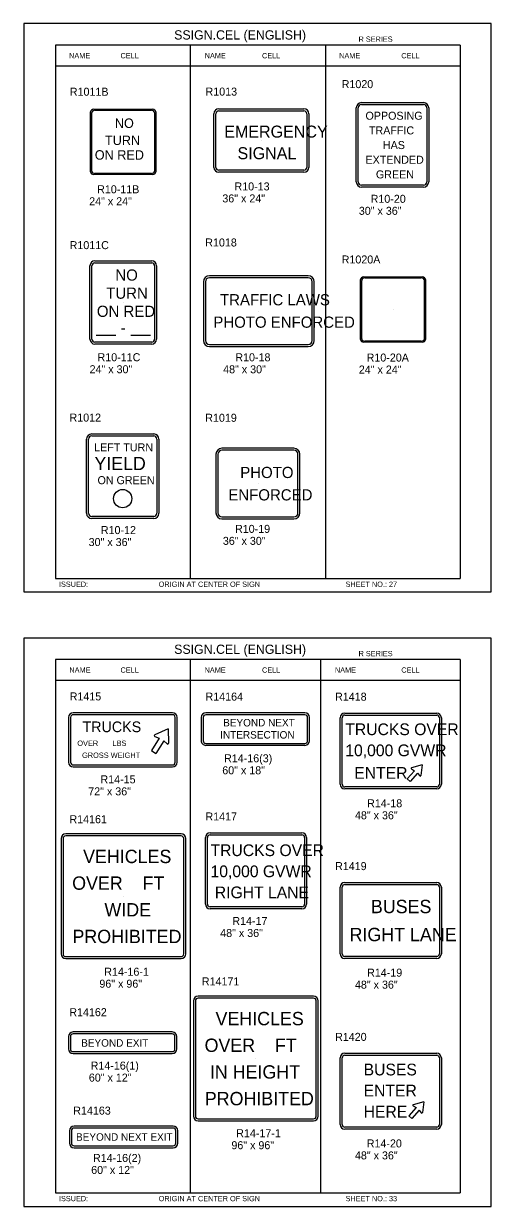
# Model space of a CAD drawing. Extents: x -5299 to 22597, y -19549 to -1808.
# Drawn here: x -3651 to -2950, y -8230 to -6456 of the extents above; entities that cross this region are included whole.
import ezdxf

# ---------------------------------------------------------------- set-up
doc = ezdxf.new("R2010")
doc.units = 0
for name, color, linetype in [('Level 1', 7, 'Continuous'), ('Level 2', 7, 'Continuous'), ('Level 3', 7, 'Continuous'), ('Level 63', 7, 'Continuous')]:
    doc.layers.add(name, color=color, linetype=linetype)

msp = doc.modelspace()

# ---------------------------------------------------------------- linework, layer by layer
at = {"layer": 'Level 1'}
for p, q in [((-2996.6, -6488.6), (-3603.6, -6488.6)), ((-3603.6, -6488.6), (-3603.6, -7288.6)), ((-3401.3, -6488.6), (-3401.3, -7288.6)), ((-3198.9, -6488.6), (-3198.9, -7288.6)), ((-2996.6, -6488.6), (-2996.6, -7288.6)), ((-2996.6, -6520.3), (-3603.6, -6520.3)), ((-3144.7, -6577.8), (-3051.8, -6577.8)), ((-3548.9, -6677.5), (-3548.9, -6589.9)), ((-3544.4, -6586.3), (-3459.5, -6586.3)), ((-3455, -6589.9), (-3455, -6677.5)), ((-3362.9, -6671.9), (-3362.9, -6591.5)), ((-3358.6, -6587.2), (-3231, -6587.2)), ((-3226.7, -6591.5), (-3226.7, -6671.9)), ((-3149.5, -6693.8), (-3149.5, -6582.6)), ((-3047, -6582.6), (-3047, -6693.8)), ((-3502, -6633.7), (-3502, -6633.7)), ((-3294.8, -6631.7), (-3294.8, -6631.7)), ((-3098.3, -6638.2), (-3098.3, -6638.2)), ((-3459.5, -6681.1), (-3544.4, -6681.1)), ((-3231, -6676.2), (-3358.6, -6676.2)), ((-3051.8, -6698.6), (-3144.7, -6698.6)), ((-3548.7, -6929.6), (-3548.7, -6819.6)), ((-3544.3, -6815.2), (-3459.2, -6815.2)), ((-3454.8, -6819.6), (-3454.8, -6929.6)), ((-3378.6, -6843.6), (-3378.6, -6931.6)), ((-3224.6, -6837.6), (-3372.6, -6837.6)), ((-3218.6, -6931.6), (-3218.6, -6843.6)), ((-3144.4, -6929), (-3144.4, -6841.4)), ((-3139.9, -6837.8), (-3055, -6837.8)), ((-3050.5, -6841.4), (-3050.5, -6929)), ((-3298.6, -6887.4), (-3298.6, -6887.4)), ((-3097.4, -6885.2), (-3097.4, -6885.2)), ((-3459.2, -6934), (-3544.3, -6934)), ((-3055, -6932.7), (-3139.9, -6932.7)), ((-3372.6, -6937.6), (-3224.6, -6937.6)), ((-3549.1, -7074.8), (-3456.2, -7074.8)), ((-3553.9, -7190.8), (-3553.9, -7079.6)), ((-3451.4, -7079.6), (-3451.4, -7190.8)), ((-3359.9, -7102.2), (-3359.9, -7190.2)), ((-3245.9, -7096.2), (-3353.9, -7096.2)), ((-3239.9, -7190.2), (-3239.9, -7102.2)), ((-3502.7, -7135.2), (-3502.7, -7135.2)), ((-3299.8, -7146.2), (-3299.8, -7146.2)), ((-3456.2, -7195.6), (-3549.1, -7195.6)), ((-3353.9, -7196.2), (-3245.9, -7196.2)), ((-3603.6, -7288.6), (-2996.6, -7288.6)), ((-2996.6, -7410), (-3603.6, -7410)), ((-3603.6, -7410), (-3603.6, -8210)), ((-3401.3, -7410), (-3401.3, -8210)), ((-3206.1, -7410), (-3206.1, -8210)), ((-2996.6, -7410), (-2996.6, -8210)), ((-2996.6, -7441.7), (-3603.6, -7441.7)), ((-3580.8, -7496.8), (-3580.8, -7564.2)), ((-3428, -7492.8), (-3576.8, -7492.8)), ((-3424, -7564.2), (-3424, -7496.8)), ((-3382, -7497), (-3382, -7531.8)), ((-3229.4, -7493), (-3378, -7493)), ((-3225.4, -7531.8), (-3225.4, -7497)), ((-3173.7, -7597.2), (-3173.7, -7497.4)), ((-3169.7, -7493.4), (-3032, -7493.4)), ((-3028, -7497.4), (-3028, -7597.2)), ((-3434.7, -7514.2), (-3454.6, -7523.1)), ((-3434.7, -7514.2), (-3434, -7535.6)), ((-3303.7, -7506.3), (-3303.7, -7506.3)), ((-3502.4, -7530.5), (-3502.4, -7530.5)), ((-3448, -7528), (-3459.6, -7546.6)), ((-3454.5, -7525.3), (-3448, -7528)), ((-3441.2, -7532.2), (-3452.8, -7550.9)), ((-3441.2, -7532.2), (-3435.9, -7536.6)), ((-3378, -7535.8), (-3229.4, -7535.8)), ((-3459.6, -7546.6), (-3452.8, -7550.9)), ((-3100.9, -7547.3), (-3100.9, -7547.3)), ((-3576.8, -7568.2), (-3428, -7568.2)), ((-3069.8, -7574), (-3065.2, -7576.8)), ((-3053.7, -7568.2), (-3069.5, -7572.4)), ((-3053.7, -7568.2), (-3055.8, -7584.1)), ((-3065.2, -7576.8), (-3076.1, -7589.2)), ((-3076.1, -7589.2), (-3071.6, -7593.1)), ((-3060.7, -7580.7), (-3071.6, -7593.1)), ((-3060.7, -7580.7), (-3057.4, -7584.6)), ((-3032, -7601.2), (-3169.7, -7601.2)), ((-3592.1, -7678.7), (-3592.1, -7851.7)), ((-3415.2, -7674.7), (-3588.1, -7674.7)), ((-3411.2, -7851.7), (-3411.2, -7678.7)), ((-3375.7, -7776.9), (-3375.7, -7677.1)), ((-3371.7, -7673.1), (-3234, -7673.1)), ((-3230, -7677.1), (-3230, -7776.9)), ((-3302.8, -7727), (-3302.8, -7727)), ((-3169.7, -7747.5), (-3032, -7747.5)), ((-3501.6, -7765.2), (-3501.6, -7765.2)), ((-3173.7, -7851.3), (-3173.7, -7751.5)), ((-3028, -7751.5), (-3028, -7851.3)), ((-3234, -7780.9), (-3371.7, -7780.9)), ((-3100.9, -7801.4), (-3100.9, -7801.4)), ((-3588.1, -7855.7), (-3415.2, -7855.7)), ((-3032, -7855.3), (-3169.7, -7855.3)), ((-3393.6, -7922), (-3393.6, -8094.9)), ((-3216.7, -7918), (-3389.6, -7918)), ((-3212.7, -8094.9), (-3212.7, -7922)), ((-3581, -7975.7), (-3581, -7994.2)), ((-3428.4, -7971.7), (-3577, -7971.7)), ((-3424.4, -7994.2), (-3424.4, -7975.7)), ((-3577, -7998.2), (-3428.4, -7998.2)), ((-3502.7, -7985), (-3502.7, -7985)), ((-3303.2, -8008.4), (-3303.2, -8008.4)), ((-3173.7, -8107.4), (-3173.7, -8007.6)), ((-3169.7, -8003.6), (-3032, -8003.6)), ((-3028, -8007.6), (-3028, -8107.4)), ((-3100.9, -8057.5), (-3100.9, -8057.5)), ((-3062.8, -8082.1), (-3073.7, -8094.5)), ((-3058.3, -8086.1), (-3069.2, -8098.5)), ((-3067.4, -8079.4), (-3062.8, -8082.1)), ((-3051.3, -8073.6), (-3067.1, -8077.7)), ((-3058.3, -8086.1), (-3055, -8090)), ((-3051.3, -8073.6), (-3053.4, -8089.5)), ((-3389.6, -8098.9), (-3216.7, -8098.9)), ((-3073.7, -8094.5), (-3069.2, -8098.5)), ((-3579.5, -8116.8), (-3579.5, -8135.3)), ((-3427, -8112.8), (-3575.5, -8112.8)), ((-3423, -8135.3), (-3423, -8116.8)), ((-3032, -8111.4), (-3169.7, -8111.4)), ((-3575.5, -8139.3), (-3427, -8139.3)), ((-3501.2, -8126.1), (-3501.2, -8126.1)), ((-3603.6, -8210), (-2996.6, -8210))]:
    msp.add_line(p, q, dxfattribs=at)
msp.add_circle((-3502.7, -7168.7), 13.7, dxfattribs=at)
for centre, radius, start, end in [((-3144.7, -6582.6), 4.8, 90, 180), ((-3051.8, -6582.6), 4.8, 0, 90), ((-3358.6, -6591.5), 4.32, 90, 180), ((-3231, -6591.5), 4.32, 0, 90), ((-3358.6, -6671.9), 4.32, 180, 270), ((-3231, -6671.9), 4.32, 270, 0), ((-3144.7, -6693.8), 4.8, 180, 270), ((-3051.8, -6693.8), 4.8, 270, 0), ((-3544.3, -6819.6), 4.4, 90, 180), ((-3459.2, -6819.6), 4.4, 0, 90), ((-3372.6, -6843.6), 6, 90, 180), ((-3224.6, -6843.6), 6, 0, 90), ((-3544.3, -6929.6), 4.4, 180, 270), ((-3459.2, -6929.6), 4.4, 270, 0), ((-3372.6, -6931.6), 6, 180, 270), ((-3224.6, -6931.6), 6, 270, 0), ((-3549.1, -7079.6), 4.8, 90, 180), ((-3456.2, -7079.6), 4.8, 0, 90), ((-3353.9, -7102.2), 6, 90, 180), ((-3245.9, -7102.2), 6, 0, 90), ((-3549.1, -7190.8), 4.8, 180, 270), ((-3456.2, -7190.8), 4.8, 270, 0), ((-3353.9, -7190.2), 6, 180, 270), ((-3245.9, -7190.2), 6, 270, 0), ((-3576.8, -7496.8), 4, 90, 180), ((-3428, -7496.8), 4, 0, 90), ((-3378, -7497), 4, 90, 180), ((-3229.4, -7497), 4, 0, 90), ((-3169.7, -7497.4), 4, 90, 180), ((-3032, -7497.4), 4, 0, 90), ((-3454.1, -7524.2), 1.2, 114.124, 248.3476), ((-3435.2, -7535.6), 1.2, 230.0779, 1.968), ((-3378, -7531.8), 4, 180.001, 270), ((-3229.4, -7531.8), 4, 270, 0), ((-3576.8, -7564.2), 4, 180, 270), ((-3428, -7564.2), 4, 270, 0), ((-3069.3, -7573.3), 0.9, 104.7504, 238.9741), ((-3056.7, -7584), 0.9, 220.7043, 352.5945), ((-3169.7, -7597.2), 4, 180, 270), ((-3032, -7597.2), 4, 270, 0), ((-3588.1, -7678.7), 4, 90, 180), ((-3415.2, -7678.7), 4, 0, 90), ((-3371.7, -7677.1), 4, 90, 180), ((-3234, -7677.1), 4, 0, 90), ((-3169.7, -7751.5), 4, 90, 180), ((-3032, -7751.5), 4, 0, 90), ((-3371.7, -7776.9), 4, 180, 270), ((-3234, -7776.9), 4, 270, 0), ((-3588.1, -7851.7), 4, 180, 270), ((-3415.2, -7851.7), 4, 270, 0), ((-3169.7, -7851.3), 4, 180, 270), ((-3032, -7851.3), 4, 270, 0), ((-3389.6, -7922), 4, 90, 180), ((-3216.7, -7922), 4, 0, 90), ((-3577, -7975.7), 4, 90, 180), ((-3428.4, -7975.7), 4, 0, 90), ((-3577, -7994.2), 4, 180, 270), ((-3428.4, -7994.2), 4, 270, 0), ((-3169.7, -8007.6), 4, 90, 180), ((-3032, -8007.6), 4, 0, 90), ((-3066.9, -8078.6), 0.9, 104.7504, 238.9741), ((-3389.6, -8094.9), 4, 180, 270), ((-3216.7, -8094.9), 4, 270, 0), ((-3054.3, -8089.4), 0.9, 220.7043, 352.5945), ((-3575.5, -8116.8), 4, 90, 180), ((-3427, -8116.8), 4, 0, 90), ((-3169.7, -8107.4), 4, 180, 270), ((-3032, -8107.4), 4, 270, 0), ((-3575.5, -8135.3), 4, 180, 270), ((-3427, -8135.3), 4, 270, 0)]:
    msp.add_arc(centre, radius, start, end, dxfattribs=at)
for centre, major_axis, start_param, end_param in [((-3544.4, -6589.9), (-4.51, 0), 4.712389, 6.283185), ((-3459.5, -6589.9), (-4.51, 0), 3.141593, 4.712389), ((-3544.4, -6677.5), (4.51, 0), 3.141593, 4.712389), ((-3459.5, -6677.5), (4.51, 0), 4.712389, 6.283185), ((-3139.9, -6841.4), (-4.51, 0), 4.712389, 6.283185), ((-3055, -6841.4), (-4.51, 0), 3.141593, 4.712389), ((-3139.9, -6929), (4.51, 0), 3.141593, 4.712389), ((-3055, -6929), (4.51, 0), 4.712389, 6.283185)]:
    msp.add_ellipse(centre, major_axis=major_axis, ratio=0.802018, start_param=start_param, end_param=end_param, dxfattribs=at)
at = {"layer": 'Level 3'}
for p, q in [((-3144.7, -6574.8), (-3051.8, -6574.8)), ((-3550.7, -6678.7), (-3550.7, -6588.7)), ((-3545.9, -6584.8), (-3458.1, -6584.8)), ((-3453.2, -6588.7), (-3453.2, -6678.7)), ((-3365.9, -6671.9), (-3365.9, -6591.5)), ((-3358.6, -6584.2), (-3231, -6584.2)), ((-3223.7, -6591.5), (-3223.7, -6671.9)), ((-3152.5, -6693.8), (-3152.5, -6582.6)), ((-3044, -6582.6), (-3044, -6693.8)), ((-3458.1, -6682.6), (-3545.9, -6682.6)), ((-3231, -6679.2), (-3358.6, -6679.2)), ((-3051.8, -6701.6), (-3144.7, -6701.6)), ((-3551.7, -6929.6), (-3551.7, -6819.6)), ((-3544.3, -6812.2), (-3459.2, -6812.2)), ((-3451.8, -6819.6), (-3451.8, -6929.6)), ((-3381.6, -6843.6), (-3381.6, -6931.6)), ((-3224.6, -6834.6), (-3372.6, -6834.6)), ((-3215.6, -6931.6), (-3215.6, -6843.6)), ((-3146.2, -6930.2), (-3146.2, -6840.2)), ((-3141.3, -6836.3), (-3053.5, -6836.3)), ((-3048.6, -6840.2), (-3048.6, -6930.2)), ((-3501.8, -6874.6), (-3501.8, -6874.6)), ((-3542.3, -6923.4), (-3513, -6923.4)), ((-3490.6, -6923.4), (-3461.2, -6923.4)), ((-3053.5, -6934.1), (-3141.3, -6934.1)), ((-3459.2, -6937), (-3544.3, -6937)), ((-3372.6, -6940.6), (-3224.6, -6940.6)), ((-3549.1, -7071.8), (-3456.2, -7071.8)), ((-3556.9, -7190.8), (-3556.9, -7079.6)), ((-3448.4, -7079.6), (-3448.4, -7190.8)), ((-3245.9, -7093.2), (-3353.9, -7093.2)), ((-3362.9, -7102.2), (-3362.9, -7190.2)), ((-3236.9, -7190.2), (-3236.9, -7102.2)), ((-3456.2, -7198.6), (-3549.1, -7198.6)), ((-3353.9, -7199.2), (-3245.9, -7199.2)), ((-3583.8, -7496.8), (-3583.8, -7564.2)), ((-3428, -7489.8), (-3576.8, -7489.8)), ((-3421, -7564.2), (-3421, -7496.8)), ((-3385, -7497), (-3385, -7531.8)), ((-3229.4, -7490), (-3378, -7490)), ((-3222.4, -7531.8), (-3222.4, -7497)), ((-3176.7, -7597.2), (-3176.7, -7497.4)), ((-3169.7, -7490.4), (-3032, -7490.4)), ((-3025, -7497.4), (-3025, -7597.2)), ((-3229.4, -7538.8), (-3378, -7538.8)), ((-3576.8, -7571.2), (-3428, -7571.2)), ((-3032, -7604.2), (-3169.7, -7604.2)), ((-3595.1, -7678.7), (-3595.1, -7851.7)), ((-3415.2, -7671.7), (-3588.1, -7671.7)), ((-3408.2, -7851.7), (-3408.2, -7678.7)), ((-3378.7, -7776.9), (-3378.7, -7677.1)), ((-3371.7, -7670.1), (-3234, -7670.1)), ((-3227, -7677.1), (-3227, -7776.9)), ((-3169.7, -7744.5), (-3032, -7744.5)), ((-3176.7, -7851.3), (-3176.7, -7751.5)), ((-3025, -7751.5), (-3025, -7851.3)), ((-3234, -7783.9), (-3371.7, -7783.9)), ((-3588.1, -7858.7), (-3415.2, -7858.7)), ((-3032, -7858.3), (-3169.7, -7858.3)), ((-3396.6, -7922), (-3396.6, -8094.9)), ((-3216.7, -7915), (-3389.6, -7915)), ((-3209.7, -8094.9), (-3209.7, -7922)), ((-3584, -7975.7), (-3584, -7994.2)), ((-3428.4, -7968.7), (-3577, -7968.7)), ((-3421.4, -7994.2), (-3421.4, -7975.7)), ((-3577, -8001.2), (-3428.4, -8001.2)), ((-3176.7, -8107.4), (-3176.7, -8007.6)), ((-3169.7, -8000.6), (-3032, -8000.6)), ((-3025, -8007.6), (-3025, -8107.4)), ((-3389.6, -8101.9), (-3216.7, -8101.9)), ((-3582.5, -8116.8), (-3582.5, -8135.3)), ((-3427, -8109.8), (-3575.5, -8109.8)), ((-3420, -8135.3), (-3420, -8116.8)), ((-3032, -8114.4), (-3169.7, -8114.4)), ((-3575.5, -8142.3), (-3427, -8142.3))]:
    msp.add_line(p, q, dxfattribs=at)
for centre, radius, start, end in [((-3144.7, -6582.6), 7.8, 90, 180), ((-3051.8, -6582.6), 7.8, 0, 90), ((-3358.6, -6591.5), 7.32, 90, 180), ((-3231, -6591.5), 7.32, 0, 90), ((-3358.6, -6671.9), 7.32, 180, 270), ((-3231, -6671.9), 7.32, 270, 0), ((-3144.7, -6693.8), 7.8, 180, 270), ((-3051.8, -6693.8), 7.8, 270, 0), ((-3544.3, -6819.6), 7.4, 90, 180), ((-3459.2, -6819.6), 7.4, 0, 90), ((-3372.6, -6843.6), 9, 90, 180), ((-3224.6, -6843.6), 9, 0, 90), ((-3544.3, -6929.6), 7.4, 180, 270), ((-3459.2, -6929.6), 7.4, 270, 0), ((-3372.6, -6931.6), 9, 180, 270), ((-3224.6, -6931.6), 9, 270, 0), ((-3549.1, -7079.6), 7.8, 90, 180), ((-3456.2, -7079.6), 7.8, 0, 90), ((-3353.9, -7102.2), 9, 90, 180), ((-3245.9, -7102.2), 9, 0, 90), ((-3549.1, -7190.8), 7.8, 180, 270), ((-3456.2, -7190.8), 7.8, 270, 0), ((-3353.9, -7190.2), 9, 180, 270), ((-3245.9, -7190.2), 9, 270, 0), ((-3576.8, -7496.8), 7, 90, 180), ((-3428, -7496.8), 7, 0, 90), ((-3378, -7497), 7, 90, 180), ((-3229.4, -7497), 7, 0, 90), ((-3169.7, -7497.4), 7, 90, 180), ((-3032, -7497.4), 7, 0, 90), ((-3378, -7531.8), 7, 179.9992, 270), ((-3229.4, -7531.8), 7, 270, 0), ((-3576.8, -7564.2), 7, 180, 270), ((-3428, -7564.2), 7, 270, 0), ((-3169.7, -7597.2), 7, 180, 270), ((-3032, -7597.2), 7, 270, 0), ((-3588.1, -7678.7), 7, 90, 180), ((-3415.2, -7678.7), 7, 0, 90), ((-3371.7, -7677.1), 7, 90, 180), ((-3234, -7677.1), 7, 0, 90), ((-3169.7, -7751.5), 7, 90, 180), ((-3032, -7751.5), 7, 0, 90), ((-3371.7, -7776.9), 7, 180, 270), ((-3234, -7776.9), 7, 270, 0), ((-3588.1, -7851.7), 7, 180, 270), ((-3415.2, -7851.7), 7, 270, 0), ((-3169.7, -7851.3), 7, 180, 270), ((-3032, -7851.3), 7, 270, 0), ((-3389.6, -7922), 7, 90, 180), ((-3216.7, -7922), 7, 0, 90), ((-3577, -7975.7), 7, 90, 180), ((-3428.4, -7975.7), 7, 0, 90), ((-3577, -7994.2), 7, 180, 270), ((-3428.4, -7994.2), 7, 270, 0), ((-3169.7, -8007.6), 7, 90, 180), ((-3032, -8007.6), 7, 0, 90), ((-3389.6, -8094.9), 7, 180, 270), ((-3216.7, -8094.9), 7, 270, 0), ((-3575.5, -8116.8), 7, 90, 180), ((-3427, -8116.8), 7, 0, 90), ((-3169.7, -8107.4), 7, 180, 270), ((-3032, -8107.4), 7, 270, 0), ((-3575.5, -8135.3), 7, 180, 270), ((-3427, -8135.3), 7, 270, 0)]:
    msp.add_arc(centre, radius, start, end, dxfattribs=at)
for centre, major_axis, start_param, end_param in [((-3545.9, -6588.7), (-4.88, 0), 4.712389, 6.283185), ((-3458.1, -6588.7), (-4.88, 0), 3.141593, 4.712389), ((-3545.9, -6678.7), (4.88, 0), 3.141593, 4.712389), ((-3458.1, -6678.7), (4.88, 0), 4.712389, 6.283185), ((-3141.3, -6840.2), (-4.88, 0), 4.712389, 6.283185), ((-3053.5, -6840.2), (-4.88, 0), 3.141593, 4.712389), ((-3141.3, -6930.2), (4.88, 0), 3.141593, 4.712389), ((-3053.5, -6930.2), (4.88, 0), 4.712389, 6.283185)]:
    msp.add_ellipse(centre, major_axis=major_axis, ratio=0.802018, start_param=start_param, end_param=end_param, dxfattribs=at)
at = {"layer": 'Level 63'}
for points in [[(-3651.1, -7308.8), (-2950.1, -7308.8), (-2950.1, -6456.4), (-3651.1, -6456.4)], [(-3651.1, -8230.2), (-2950.1, -8230.2), (-2950.1, -7377.8), (-3651.1, -7377.8)]]:
    msp.add_lwpolyline(points, close=True, dxfattribs=at)

# ---------------------------------------------------------------- texts
at = {"layer": 'Level 1'}
for s, height, p in [('NO', 14.18, (-3514.4, -6612.8)), ('TURN', 14.18, (-3529.2, -6638.4)), ('ON RED', 14.18, (-3544.5, -6660.4)), ('TRAFFIC LAWS', 16.8, (-3356.8, -6878.9)), ('PHOTO ENFORCED', 16.8, (-3366.8, -6912.5)), ('LEFT TURN', 12, (-3545.4, -7097.8)), ('YIELD', 19.91, (-3545, -7126)), ('PHOTO', 16.8, (-3326.5, -7137.9)), ('ON GREEN', 12, (-3540.4, -7147.1)), ('ENFORCED', 16.8, (-3344.3, -7171.5)), ('TRUCKS', 16, (-3562.9, -7519)), ('BEYOND NEXT', 11.2, (-3352.1, -7510.4)), ('INTERSECTION', 11.2, (-3356.5, -7528.6)), ('TRUCKS OVER', 17.6, (-3169, -7523.5)), ('OVER       LBS', 8, (-3570.7, -7539.6)), ('10,000 GVWR', 17.6, (-3169, -7555.1)), ('GROSS WEIGHT', 8, (-3563.6, -7557.6)), ('ENTER', 17.6, (-3155.5, -7589)), ('VEHICLES', 20, (-3562, -7715.4)), ('TRUCKS OVER', 17.6, (-3371, -7704.9)), ('10,000 GVWR', 17.6, (-3371, -7736.5)), ('OVER    FT', 20, (-3578.4, -7755.4)), ('RIGHT LANE', 17.6, (-3364.6, -7768.1)), ('WIDE', 20, (-3530, -7795.4)), ('BUSES', 20, (-3130.6, -7790.5)), ('PROHIBITED', 20, (-3578, -7835.4)), ('RIGHT LANE', 20, (-3162.6, -7832.5)), ('VEHICLES', 20, (-3363.5, -7958.6)), ('BEYOND EXIT   ', 11.2, (-3564.9, -7990.7)), ('OVER    FT', 20, (-3379.9, -7998.6)), ('BUSES', 17.6, (-3141.5, -8033.8)), ('IN HEIGHT', 20, (-3371.9, -8038.6)), ('ENTER', 17.6, (-3141.5, -8065.4)), ('PROHIBITED', 20, (-3379.6, -8078.6)), ('HERE', 17.6, (-3141.5, -8097)), ('BEYOND NEXT EXIT', 11.2, (-3572.6, -8131.8))]:
    msp.add_text(s, height=height, dxfattribs=at).set_placement(p)
at = {"layer": 'Level 2'}
for s, p in [('R1020', (-3174.4, -6553.1)), ('R1011B', (-3581.9, -6564.5)), ('R1013', (-3378.5, -6564.3)), ('R10-11B', (-3541, -6710.8)), ('R10-13', (-3335.1, -6706.5)), ('24" x 24"', (-3552.9, -6728.8)), ('36" x 24"', (-3353.3, -6724.5)), ('R10-20', (-3131, -6725.1)), ('30" x 36"', (-3148.7, -6743.1)), ('R1011C', (-3582.2, -6794.6)), ('R1018', (-3378.9, -6790.6)), ('R1020A', (-3174.4, -6816.1)), ('R10-11C', (-3540.4, -6962.7)), ('R10-18', (-3333.8, -6962.8)), ('R10-20A', (-3137, -6963.2)), ('24" x 30"', (-3552.3, -6980.7)), ('48" x 30"', (-3352.1, -6980.8)), ('24" x 24"', (-3148.7, -6981.2)), ('R1012', (-3582.4, -7053.2)), ('R1019', (-3378.9, -7053.5)), ('R10-12', (-3535.4, -7221.9)), ('R10-19', (-3334.3, -7220.1)), ('30" x 36"', (-3553.7, -7239.9)), ('36" x 30"', (-3352.5, -7238.1)), ('R1415', (-3582.1, -7471.4)), ('R14164', (-3378.5, -7471.7)), ('R1418', (-3184.3, -7471.8)), ('R14-16(3)', (-3350.7, -7564.2)), ('60" x 18"', (-3353.4, -7582.2)), ('R14-15', (-3536, -7595.8)), ('72" x 36"', (-3554.3, -7613.8)), ('R14-18', (-3136.3, -7631.7)), ('R14161', (-3582.5, -7655.6)), ('R1417', (-3378.6, -7651.5)), ('48" x 36"', (-3154.5, -7649.7)), ('R1419', (-3184.3, -7725.9)), ('R14-17', (-3338.3, -7808.2)), ('48" x 36"', (-3356.5, -7826.2)), ('R14-16-1', (-3530.3, -7884.3)), ('R14-19', (-3136.3, -7885.7)), ('96" x 96"', (-3537.6, -7902.3)), ('R14171', (-3384, -7898.8)), ('48" x 36"', (-3154.5, -7903.7)), ('R14162', (-3582.7, -7945)), ('R1420', (-3184.3, -7982)), ('R14-16(1)', (-3550.7, -8025.1)), ('60" x 12"', (-3553.4, -8043.1)), ('R14163', (-3576.8, -8092.6)), ('R14-17-1', (-3332.5, -8126.5)), ('96" x 96"', (-3339.7, -8144.5)), ('R14-20', (-3136.8, -8141.8)), ('R14-16(2)', (-3547.2, -8163.6)), ('48" x 36"', (-3154.5, -8159.8)), ('60" x 12"', (-3549.9, -8181.6))]:
    msp.add_text(s, height=12, dxfattribs=at).set_placement(p)
at = {"layer": 'Level 3'}
for s, height, p in [('SSIGN.CEL (ENGLISH)', 13.857, (-3425.5, -6480.2)), ('R SERIES', 7.92, (-3149.1, -6483.6)), ('NAME', 7.92, (-3583, -6508.4)), ('CELL', 7.92, (-3505.9, -6508.4)), ('NAME', 7.92, (-3379.7, -6508.4)), ('CELL', 7.92, (-3293.8, -6508.4)), ('NAME', 7.92, (-3178.2, -6508.4)), ('CELL', 7.92, (-3085, -6508.4)), ('OPPOSING', 12, (-3138.7, -6600.5)), ('EMERGENCY', 18, (-3350.5, -6627.3)), ('TRAFFIC', 12, (-3133.5, -6622.5)), ('HAS', 12, (-3112.6, -6644.5)), ('SIGNAL', 18, (-3330.6, -6659.7)), ('EXTENDED', 12, (-3138.7, -6666.5)), ('GREEN', 12, (-3123.1, -6688.5)), ('NO', 16.8, (-3513.7, -6841.8)), ('TURN', 16.8, (-3527.4, -6869)), ('ON RED', 16.8, (-3541.4, -6896.2)), ('-', 16.8, (-3505.9, -6921)), ('ISSUED:', 7.92, (-3598.2, -7301.1)), ('ORIGIN AT CENTER OF SIGN', 7.918, (-3448.7, -7301.1)), ('SHEET NO.: 27', 7.918, (-3168.5, -7301.1)), ('SSIGN.CEL (ENGLISH)', 13.857, (-3425.5, -7401.6)), ('R SERIES', 7.92, (-3149.1, -7405.1)), ('NAME', 7.92, (-3582.5, -7429.8)), ('CELL', 7.92, (-3505.9, -7429.8)), ('NAME', 7.92, (-3379.9, -7429.8)), ('CELL', 7.92, (-3293.8, -7429.8)), ('NAME', 7.92, (-3184.5, -7429.8)), ('CELL', 7.92, (-3085, -7429.8)), ('ISSUED:', 7.92, (-3598.2, -8222.5)), ('ORIGIN AT CENTER OF SIGN', 7.918, (-3448.7, -8222.5)), ('SHEET NO.: 33', 7.918, (-3168.5, -8222.5))]:
    msp.add_text(s, height=height, dxfattribs=at).set_placement(p)

doc.saveas('drawing.dxf')
